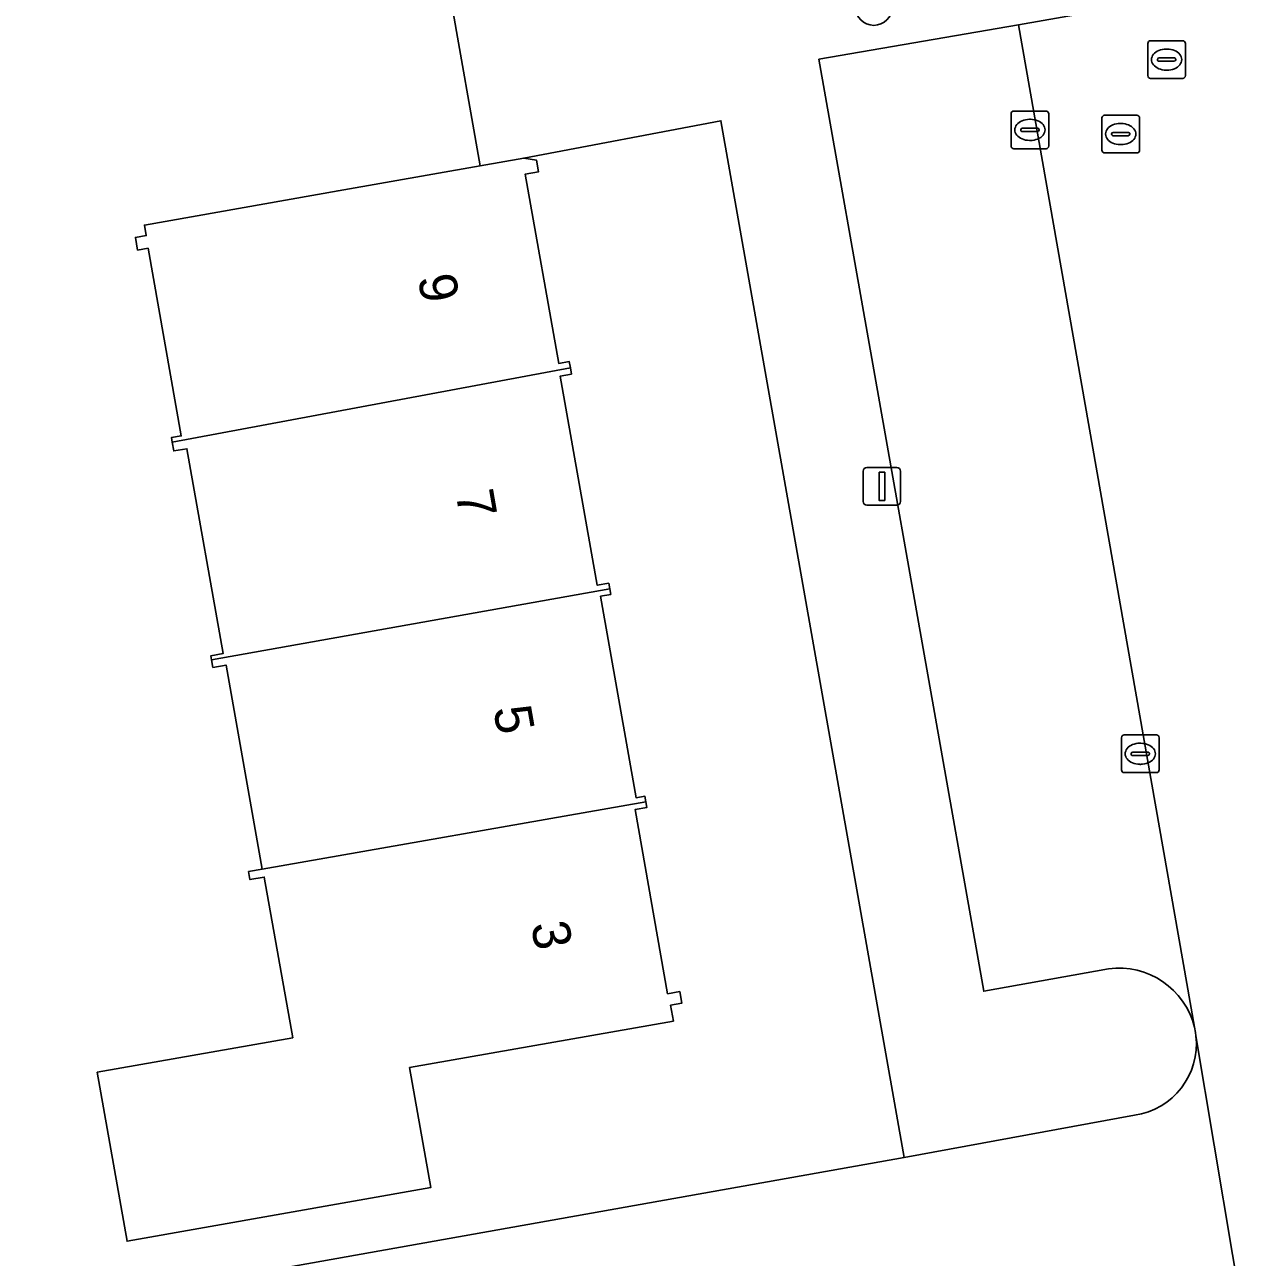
# Model space of a CAD drawing. Extents: x 157793 to 159380, y 380877 to 382313.
# Drawn here: x 158414.16 to 158446.96, y 381341.14 to 381373.82 of the extents above; entities that cross this region are included whole.
import ezdxf

# ---------------------------------------------------------------- set-up
doc = ezdxf.new("R2010")
doc.units = 0
for name, color, linetype in [('IMGEO_Boom', 7, 'Continuous'), ('IMGEO_Erf', 7, 'Continuous'), ('IMGEO_Kolk', 7, 'Continuous'), ('IMGEO_Lichtmast', 7, 'Continuous'), ('IMGEO_Pand', 7, 'Continuous'), ('IMGEO_Pand_nummerreeks', 7, 'Continuous'), ('IMGEO_Parkeervlak_open', 7, 'Continuous'), ('IMGEO_Rijbaan_lokaal_open', 7, 'Continuous'), ('IMGEO_Rioolput', 7, 'Continuous'), ('IMGEO_Voetpad_open', 7, 'Continuous')]:
    doc.layers.add(name, color=color, linetype=linetype)

msp = doc.modelspace()

# ---------------------------------------------------------------- linework, layer by layer
at = {"layer": 'IMGEO_Boom'}
msp.add_circle((158436.685, 381374.292), 0.489, dxfattribs=at)
at = {"layer": 'IMGEO_Erf'}
for points in [[(158418.462, 381362.577), (158418.114, 381362.516), (158418.072, 381362.754), (158418.051, 381362.871), (158418.313, 381362.917), (158417.434, 381367.893), (158417.154, 381367.844), (158417.095, 381368.178), (158417.385, 381368.229), (158417.336, 381368.507), (158422.475, 381369.415), (158426.243, 381370.08), (158425.473, 381374.444), (158423.856, 381383.494), (158422.382, 381391.739), (158421.482, 381396.777), (158418.518, 381396.255), (158409.932, 381394.841)], [(158415.288, 381339.829), (158437.487, 381343.779), (158432.629, 381371.271), (158427.398, 381370.284), (158427.741, 381370.226), (158427.794, 381369.922), (158427.44, 381369.859), (158428.327, 381364.837), (158428.606, 381364.886), (158428.636, 381364.72), (158428.665, 381364.555), (158428.368, 381364.503), (158429.348, 381358.957), (158429.656, 381359.011), (158429.682, 381358.863), (158429.709, 381358.713), (158429.437, 381358.665), (158430.381, 381353.319), (158430.615, 381353.36), (158430.641, 381353.213), (158430.667, 381353.063), (158430.351, 381353.007), (158431.213, 381348.125), (158431.536, 381348.182), (158431.591, 381347.872), (158431.295, 381347.82), (158431.369, 381347.4), (158424.37, 381346.164), (158424.932, 381342.983), (158416.874, 381341.56), (158416.083, 381346.042), (158421.27, 381346.958), (158420.517, 381351.218), (158420.135, 381351.15), (158420.098, 381351.362), (158420.458, 381351.425), (158419.501, 381356.838), (158419.155, 381356.777), (158419.119, 381356.982), (158419.1, 381357.087), (158419.422, 381357.143), (158418.462, 381362.577)]]:
    msp.add_lwpolyline(points, dxfattribs=at)
at = {"layer": 'IMGEO_Kolk'}
for p, q in [((158440.327, 381370.605), (158440.327, 381371.457)), ((158440.402, 381371.531), (158441.254, 381371.531)), ((158440.815, 381371.311), (158440.84, 381371.311)), ((158441.328, 381371.457), (158441.328, 381370.605)), ((158440.586, 381371.025), (158440.586, 381371.037)), ((158441.024, 381370.988), (158440.626, 381370.988)), ((158440.629, 381371.074), (158441.027, 381371.074)), ((158441.07, 381371.037), (158441.07, 381371.025)), ((158440.838, 381370.751), (158440.813, 381370.751)), ((158441.254, 381370.531), (158440.402, 381370.531)), ((158443.255, 381354.061), (158443.255, 381354.913)), ((158443.33, 381354.987), (158444.182, 381354.987)), ((158444.256, 381354.913), (158444.256, 381354.061)), ((158443.743, 381354.767), (158443.768, 381354.767)), ((158443.514, 381354.481), (158443.514, 381354.493)), ((158443.952, 381354.444), (158443.554, 381354.444)), ((158443.557, 381354.53), (158443.955, 381354.53)), ((158443.998, 381354.493), (158443.998, 381354.481)), ((158444.182, 381353.987), (158443.33, 381353.987)), ((158443.766, 381354.207), (158443.741, 381354.207))]:
    msp.add_line(p, q, dxfattribs=at)
for points in [[(158440.327, 381370.605), (158440.327, 381371.457)], [(158440.402, 381371.531), (158441.254, 381371.531)], [(158441.328, 381371.457), (158441.328, 381370.605)], [(158441.254, 381370.531), (158440.402, 381370.531)], [(158443.255, 381354.061), (158443.255, 381354.913)], [(158443.33, 381354.987), (158444.182, 381354.987)], [(158444.256, 381354.913), (158444.256, 381354.061)], [(158444.182, 381353.987), (158443.33, 381353.987)]]:
    msp.add_lwpolyline(points, dxfattribs=at)
for centre, radius, start, end in [((158440.404, 381371.455), 0.0765, 91.552, 178.448), ((158440.404, 381371.455), 0.0765, 91.552, 178.448), ((158441.252, 381371.455), 0.0765, 1.552, 88.448), ((158441.252, 381371.455), 0.0765, 1.552, 88.448), ((158440.626, 381371.034), 0.0403, 85.8775, 175.7526), ((158440.623, 381371.024), 0.0366, 178.938, 274.7102), ((158441.027, 381371.031), 0.043, 264.8664, 352.4533), ((158441.031, 381371.036), 0.0386, 1.7309, 96.639), ((158440.404, 381370.607), 0.0765, 181.552, 268.448), ((158440.404, 381370.607), 0.0765, 181.552, 268.448), ((158441.252, 381370.607), 0.0765, 271.552, 358.448), ((158441.252, 381370.607), 0.0765, 271.552, 358.448), ((158443.332, 381354.911), 0.0765, 91.552, 178.448), ((158443.332, 381354.911), 0.0765, 91.552, 178.448), ((158444.18, 381354.911), 0.0765, 1.552, 88.448), ((158444.18, 381354.911), 0.0765, 1.552, 88.448), ((158443.554, 381354.49), 0.0403, 85.8775, 175.7526), ((158443.551, 381354.48), 0.0366, 178.938, 274.7102), ((158443.955, 381354.487), 0.043, 264.8664, 352.4533), ((158443.959, 381354.492), 0.0386, 1.7309, 96.639), ((158443.332, 381354.063), 0.0765, 181.552, 268.448), ((158443.332, 381354.063), 0.0765, 181.552, 268.448), ((158444.18, 381354.063), 0.0765, 271.552, 358.448), ((158444.18, 381354.063), 0.0765, 271.552, 358.448)]:
    msp.add_arc(centre, radius, start, end, dxfattribs=at)
for centre, major_axis, ratio, start_param, end_param in [((158440.814, 381371.031), (-0.387, 0.002), 0.722429, 4.712389, 7.853982), ((158440.839, 381371.031), (-0.39, 0.002), 0.717154, 1.570796, 4.712389), ((158443.742, 381354.487), (-0.387, 0.002), 0.722429, 4.712389, 7.853982), ((158443.767, 381354.487), (-0.39, 0.002), 0.717154, 1.570796, 4.712389)]:
    msp.add_ellipse(centre, major_axis=major_axis, ratio=ratio, start_param=start_param, end_param=end_param, dxfattribs=at)
at = {"layer": 'IMGEO_Lichtmast'}
for p, q in [((158436.404, 381361.179), (158436.404, 381361.979)), ((158436.404, 381361.979), (158436.404, 381361.179)), ((158436.504, 381362.079), (158437.294, 381362.079)), ((158437.294, 381362.079), (158436.504, 381362.079)), ((158437.394, 381361.979), (158437.394, 381361.179)), ((158437.394, 381361.179), (158437.394, 381361.979)), ((158437.294, 381361.079), (158436.504, 381361.079)), ((158436.504, 381361.079), (158437.294, 381361.079))]:
    msp.add_line(p, q, dxfattribs=at)
msp.add_lwpolyline([(158436.824, 381361.954), (158436.974, 381361.954), (158436.974, 381361.204), (158436.824, 381361.204), (158436.824, 381361.954)], dxfattribs=at)
for centre, start, end in [((158436.504, 381361.979), 90, 180), ((158436.504, 381361.979), 90, 180), ((158437.294, 381361.979), 0, 90), ((158437.294, 381361.979), 360, 90), ((158436.504, 381361.179), 180, 270), ((158436.504, 381361.179), 180, 270), ((158437.294, 381361.179), 270, 0), ((158437.294, 381361.179), 270, 0)]:
    msp.add_arc(centre, 0.1, start, end, dxfattribs=at)
at = {"layer": 'IMGEO_Pand'}
for points in [[(158428.636, 381364.72), (158428.606, 381364.886), (158428.327, 381364.837), (158427.44, 381369.859), (158427.794, 381369.922), (158427.741, 381370.226), (158427.398, 381370.284), (158426.243, 381370.08), (158422.475, 381369.415), (158417.336, 381368.507), (158417.385, 381368.229), (158417.095, 381368.178), (158417.154, 381367.844), (158417.434, 381367.893), (158418.313, 381362.917), (158418.051, 381362.871), (158418.072, 381362.754)], [(158419.119, 381356.982), (158429.682, 381358.863), (158429.656, 381359.011), (158429.348, 381358.957), (158428.368, 381364.503), (158428.665, 381364.555), (158428.636, 381364.72), (158418.072, 381362.754), (158418.114, 381362.516), (158418.462, 381362.577), (158419.422, 381357.143), (158419.1, 381357.087)], [(158429.437, 381358.665), (158429.709, 381358.713), (158429.682, 381358.863), (158419.119, 381356.982), (158419.155, 381356.777), (158419.501, 381356.838), (158420.458, 381351.425), (158430.641, 381353.213), (158430.615, 381353.36), (158430.381, 381353.319)], [(158431.536, 381348.182), (158431.213, 381348.125), (158430.351, 381353.007), (158430.667, 381353.063), (158430.641, 381353.213), (158420.458, 381351.425), (158420.098, 381351.362), (158420.135, 381351.15), (158420.517, 381351.218), (158421.27, 381346.958), (158416.083, 381346.042), (158416.874, 381341.56), (158424.932, 381342.983), (158424.37, 381346.164), (158431.369, 381347.4), (158431.295, 381347.82), (158431.591, 381347.872)]]:
    msp.add_lwpolyline(points, close=True, dxfattribs=at)
at = {"layer": 'IMGEO_Parkeervlak_open'}
for points in [[(158440.528, 381373.814), (158435.23, 381372.903), (158439.604, 381348.192), (158442.91, 381348.784)], [(158445.193, 381347.236), (158440.528, 381373.814)]]:
    msp.add_lwpolyline(points, dxfattribs=at)
msp.add_arc((158443.19, 381346.739), 2.064, 13.9235, 97.7976, dxfattribs=at)
at = {"layer": 'IMGEO_Rijbaan_lokaal_open'}
for points in [[(158505.213, 381385.172), (158504.063, 381384.916), (158476.602, 381380.158), (158440.528, 381373.814), (158445.193, 381347.236), (158445.222, 381347.098), (158445.233, 381347.012), (158446.688, 381338.314), (158447.454, 381334.427), (158452.57, 381335.311), (158451.692, 381340.294), (158450.847, 381345.084), (158450.524, 381346.918), (158449.648, 381351.886), (158449.222, 381354.283), (158448.428, 381358.713), (158447.508, 381363.857)], [(158446.688, 381338.314), (158445.233, 381347.012)], [(158443.603, 381344.906), (158437.487, 381343.779), (158415.288, 381339.829), (158416.206, 381334.702), (158439.445, 381338.78), (158444.501, 381339.766)]]:
    msp.add_lwpolyline(points, dxfattribs=at)
msp.add_arc((158443.332, 381346.799), 1.913, 278.1395, 6.3823, dxfattribs=at)
at = {"layer": 'IMGEO_Rioolput'}
for p, q in [((158443.953, 381372.469), (158443.953, 381373.321)), ((158444.028, 381373.395), (158444.88, 381373.395)), ((158444.954, 381373.321), (158444.954, 381372.469)), ((158444.255, 381372.938), (158444.653, 381372.938)), ((158444.441, 381373.175), (158444.466, 381373.175)), ((158444.212, 381372.889), (158444.212, 381372.901)), ((158444.65, 381372.852), (158444.252, 381372.852)), ((158444.464, 381372.615), (158444.439, 381372.615)), ((158444.696, 381372.901), (158444.696, 381372.889)), ((158444.88, 381372.395), (158444.028, 381372.395)), ((158442.735, 381370.494), (158442.735, 381371.346)), ((158442.81, 381371.42), (158443.662, 381371.42)), ((158443.736, 381371.346), (158443.736, 381370.494)), ((158443.037, 381370.963), (158443.435, 381370.963)), ((158443.223, 381371.2), (158443.248, 381371.2)), ((158442.994, 381370.914), (158442.994, 381370.926)), ((158443.432, 381370.877), (158443.034, 381370.877)), ((158443.246, 381370.64), (158443.221, 381370.64)), ((158443.478, 381370.926), (158443.478, 381370.914)), ((158443.662, 381370.42), (158442.81, 381370.42))]:
    msp.add_line(p, q, dxfattribs=at)
for points in [[(158443.953, 381372.469), (158443.953, 381373.321)], [(158444.028, 381373.395), (158444.88, 381373.395)], [(158444.954, 381373.321), (158444.954, 381372.469)], [(158444.88, 381372.395), (158444.028, 381372.395)], [(158442.735, 381370.494), (158442.735, 381371.346)], [(158442.81, 381371.42), (158443.662, 381371.42)], [(158443.736, 381371.346), (158443.736, 381370.494)], [(158443.662, 381370.42), (158442.81, 381370.42)]]:
    msp.add_lwpolyline(points, dxfattribs=at)
for centre, radius, start, end in [((158444.03, 381373.319), 0.0765, 91.552, 178.448), ((158444.03, 381373.319), 0.0765, 91.552, 178.448), ((158444.878, 381373.319), 0.0765, 1.552, 88.448), ((158444.878, 381373.319), 0.0765, 1.552, 88.448), ((158444.252, 381372.898), 0.0403, 85.8775, 175.7526), ((158444.657, 381372.9), 0.0386, 1.7309, 96.639), ((158444.249, 381372.888), 0.0366, 178.938, 274.7102), ((158444.653, 381372.895), 0.043, 264.8664, 352.4533), ((158444.03, 381372.471), 0.0765, 181.552, 268.448), ((158444.03, 381372.471), 0.0765, 181.552, 268.448), ((158444.878, 381372.471), 0.0765, 271.552, 358.448), ((158444.878, 381372.471), 0.0765, 271.552, 358.448), ((158442.812, 381371.344), 0.0765, 91.552, 178.448), ((158442.812, 381371.344), 0.0765, 91.552, 178.448), ((158443.66, 381371.344), 0.0765, 1.552, 88.448), ((158443.66, 381371.344), 0.0765, 1.552, 88.448), ((158443.034, 381370.923), 0.0403, 85.8775, 175.7526), ((158443.439, 381370.925), 0.0386, 1.7309, 96.639), ((158443.031, 381370.913), 0.0366, 178.938, 274.7102), ((158443.435, 381370.92), 0.043, 264.8664, 352.4533), ((158442.812, 381370.496), 0.0765, 181.552, 268.448), ((158442.812, 381370.496), 0.0765, 181.552, 268.448), ((158443.66, 381370.496), 0.0765, 271.552, 358.448), ((158443.66, 381370.496), 0.0765, 271.552, 358.448)]:
    msp.add_arc(centre, radius, start, end, dxfattribs=at)
for centre, major_axis, ratio, start_param, end_param in [((158444.44, 381372.895), (-0.387, 0.002), 0.722429, 4.712389, 7.853982), ((158444.465, 381372.895), (-0.39, 0.002), 0.717154, 1.570796, 4.712389), ((158443.222, 381370.92), (-0.387, 0.002), 0.722429, 4.712389, 7.853982), ((158443.247, 381370.92), (-0.39, 0.002), 0.717154, 1.570796, 4.712389)]:
    msp.add_ellipse(centre, major_axis=major_axis, ratio=ratio, start_param=start_param, end_param=end_param, dxfattribs=at)
at = {"layer": 'IMGEO_Voetpad_open'}
for points in [[(158442.91, 381348.784), (158439.604, 381348.192), (158435.23, 381372.903), (158440.528, 381373.814), (158476.602, 381380.158)], [(158425.473, 381374.444), (158426.243, 381370.08), (158427.398, 381370.284), (158432.629, 381371.271), (158437.487, 381343.779), (158443.603, 381344.906)], [(158445.233, 381347.012), (158445.222, 381347.098), (158445.193, 381347.236)]]:
    msp.add_lwpolyline(points, dxfattribs=at)
for centre, radius, start, end in [((158443.19, 381346.739), 2.064, 13.9235, 97.7976), ((158443.332, 381346.799), 1.913, 278.1395, 6.3823)]:
    msp.add_arc(centre, radius, start, end, dxfattribs=at)

# ---------------------------------------------------------------- texts
at = {"layer": 'IMGEO_Pand_nummerreeks'}
for s, rotation, p in [('9', 279.926, (158424.587, 381367.125)), ('7', 279.926, (158425.588, 381361.405)), ('5', 279.9234, (158426.589, 381355.685)), ('3', 279.9234, (158427.59, 381349.966))]:
    msp.add_text(s, height=1, rotation=rotation, dxfattribs=at).set_placement(p)

doc.saveas('drawing.dxf')
